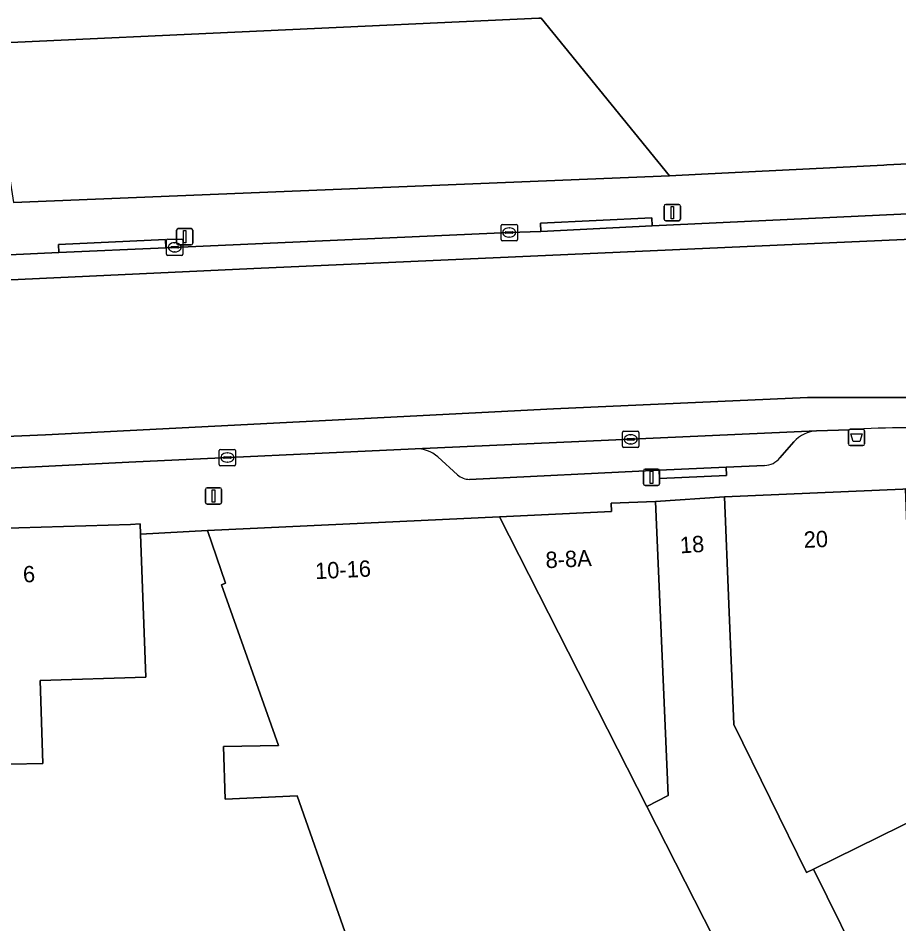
# Model space of a CAD drawing. Extents: x 161087 to 161926, y 382572 to 383873.
# Drawn here: x 161793.5 to 161847.4, y 382804.9 to 382860.4 of the extents above; entities that cross this region are included whole.
import ezdxf

# ---------------------------------------------------------------- set-up
doc = ezdxf.new("R2010")
doc.units = 0
for name, color, linetype in [('IMGEO_Afvalbak', 7, 'Continuous'), ('IMGEO_Erf', 7, 'Continuous'), ('IMGEO_Kolk', 7, 'Continuous'), ('IMGEO_Lichtmast', 7, 'Continuous'), ('IMGEO_Pand', 7, 'Continuous'), ('IMGEO_Pand_nummerreeks', 7, 'Continuous'), ('IMGEO_Parkeervlak_open', 7, 'Continuous'), ('IMGEO_Rijbaan_lokaal_gesloten', 7, 'Continuous'), ('IMGEO_Voetpad_open', 7, 'Continuous')]:
    doc.layers.add(name, color=color, linetype=linetype)

msp = doc.modelspace()

# ---------------------------------------------------------------- linework, layer by layer
at = {"layer": 'IMGEO_Afvalbak'}
for p, q in [((161844.265, 382834.304), (161844.265, 382835.104)), ((161844.265, 382835.104), (161844.265, 382834.304)), ((161844.365, 382835.204), (161845.155, 382835.204)), ((161845.155, 382835.204), (161844.365, 382835.204)), ((161845.255, 382835.104), (161845.255, 382834.304)), ((161845.255, 382834.304), (161845.255, 382835.104)), ((161845.155, 382834.204), (161844.365, 382834.204)), ((161844.365, 382834.204), (161845.155, 382834.204))]:
    msp.add_line(p, q, dxfattribs=at)
msp.add_lwpolyline([(161844.408, 382834.918), (161845.112, 382834.918), (161844.963, 382834.448), (161844.557, 382834.448), (161844.408, 382834.918)], dxfattribs=at)
for centre, start, end in [((161844.365, 382835.104), 90, 180), ((161844.365, 382835.104), 90, 180), ((161845.155, 382835.104), 0, 90), ((161845.155, 382835.104), 360, 90), ((161844.365, 382834.304), 180, 270), ((161844.365, 382834.304), 180, 270), ((161845.155, 382834.304), 270, 0), ((161845.155, 382834.304), 270, 0)]:
    msp.add_arc(centre, 0.1, start, end, dxfattribs=at)
at = {"layer": 'IMGEO_Erf'}
for points in [[(161833.32, 382850.708), (161825.459, 382860.359), (161825.324, 382860.352), (161791.643, 382858.806), (161793.173, 382849.087)], [(161852.198, 382804.529), (161855.299, 382804.359), (161860.305, 382804.076), (161860.365, 382805.353), (161855.823, 382805.577), (161852.005, 382813.152), (161851.488, 382812.897), (161842.133, 382808.291), (161845.493, 382801.467), (161846.073, 382800.288), (161849.93, 382792.454), (161851.597, 382792.363)]]:
    msp.add_lwpolyline(points, close=True, dxfattribs=at)
msp.add_lwpolyline([(161822.714, 382743.348), (161811.318, 382763.682), (161808.664, 382768.534), (161824.514, 382775.865), (161826.285, 382772.036), (161846.952, 382781.596), (161845.17, 382785.236), (161839.913, 382795.976), (161819.584, 382787.007), (161810.521, 382812.78), (161806.114, 382812.578), (161806.021, 382815.797), (161809.397, 382815.85), (161805.892, 382825.687), (161806.149, 382825.781), (161805.053, 382829.003), (161800.95, 382828.783), (161801.106, 382824.375), (161801.26, 382820.026), (161794.798, 382819.842), (161794.957, 382814.762), (161790.979, 382814.663)], dxfattribs=at)
at = {"layer": 'IMGEO_Kolk'}
for p, q in [((161823.007, 382846.814), (161823.007, 382847.666)), ((161823.082, 382847.74), (161823.934, 382847.74)), ((161823.495, 382847.52), (161823.52, 382847.52)), ((161824.008, 382847.666), (161824.008, 382846.814)), ((161823.266, 382847.234), (161823.266, 382847.246)), ((161823.704, 382847.197), (161823.306, 382847.197)), ((161823.309, 382847.283), (161823.707, 382847.283)), ((161823.518, 382846.96), (161823.493, 382846.96)), ((161823.75, 382847.246), (161823.75, 382847.234)), ((161802.539, 382845.911), (161802.539, 382846.763)), ((161802.614, 382846.837), (161803.466, 382846.837)), ((161803.027, 382846.617), (161803.052, 382846.617)), ((161803.54, 382846.763), (161803.54, 382845.911)), ((161823.934, 382846.74), (161823.082, 382846.74)), ((161803.466, 382845.837), (161802.614, 382845.837)), ((161802.798, 382846.331), (161802.798, 382846.343)), ((161803.236, 382846.294), (161802.838, 382846.294)), ((161802.841, 382846.38), (161803.239, 382846.38)), ((161803.05, 382846.057), (161803.025, 382846.057)), ((161803.282, 382846.343), (161803.282, 382846.331)), ((161830.441, 382834.163), (161830.441, 382835.015)), ((161830.516, 382835.089), (161831.368, 382835.089)), ((161830.929, 382834.869), (161830.954, 382834.869)), ((161831.442, 382835.015), (161831.442, 382834.163)), ((161830.7, 382834.583), (161830.7, 382834.595)), ((161831.138, 382834.546), (161830.74, 382834.546)), ((161830.743, 382834.632), (161831.141, 382834.632)), ((161830.952, 382834.309), (161830.927, 382834.309)), ((161831.184, 382834.595), (161831.184, 382834.583)), ((161805.757, 382833.047), (161805.757, 382833.899)), ((161805.832, 382833.973), (161806.684, 382833.973)), ((161806.245, 382833.753), (161806.27, 382833.753)), ((161806.758, 382833.899), (161806.758, 382833.047)), ((161831.368, 382834.089), (161830.516, 382834.089)), ((161806.016, 382833.467), (161806.016, 382833.479)), ((161806.454, 382833.43), (161806.056, 382833.43)), ((161806.059, 382833.516), (161806.457, 382833.516)), ((161806.268, 382833.193), (161806.243, 382833.193)), ((161806.5, 382833.479), (161806.5, 382833.467)), ((161806.684, 382832.973), (161805.832, 382832.973))]:
    msp.add_line(p, q, dxfattribs=at)
for points in [[(161823.007, 382846.814), (161823.007, 382847.666)], [(161823.082, 382847.74), (161823.934, 382847.74)], [(161824.008, 382847.666), (161824.008, 382846.814)], [(161802.539, 382845.911), (161802.539, 382846.763)], [(161802.614, 382846.837), (161803.466, 382846.837)], [(161803.54, 382846.763), (161803.54, 382845.911)], [(161823.934, 382846.74), (161823.082, 382846.74)], [(161803.466, 382845.837), (161802.614, 382845.837)], [(161830.441, 382834.163), (161830.441, 382835.015)], [(161830.516, 382835.089), (161831.368, 382835.089)], [(161831.442, 382835.015), (161831.442, 382834.163)], [(161805.757, 382833.047), (161805.757, 382833.899)], [(161805.832, 382833.973), (161806.684, 382833.973)], [(161806.758, 382833.899), (161806.758, 382833.047)], [(161831.368, 382834.089), (161830.516, 382834.089)], [(161806.684, 382832.973), (161805.832, 382832.973)]]:
    msp.add_lwpolyline(points, dxfattribs=at)
for centre, radius, start, end in [((161823.084, 382847.664), 0.0765, 91.552, 178.448), ((161823.084, 382847.664), 0.0765, 91.552, 178.448), ((161823.932, 382847.664), 0.0765, 1.552, 88.448), ((161823.932, 382847.664), 0.0765, 1.552, 88.448), ((161823.306, 382847.243), 0.0403, 85.8775, 175.7526), ((161823.303, 382847.233), 0.0366, 178.938, 274.7102), ((161823.707, 382847.24), 0.043, 264.8664, 352.4533), ((161823.711, 382847.245), 0.0386, 1.7309, 96.639), ((161802.616, 382846.761), 0.0765, 91.552, 178.448), ((161802.616, 382846.761), 0.0765, 91.552, 178.448), ((161803.464, 382846.761), 0.0765, 1.552, 88.448), ((161803.464, 382846.761), 0.0765, 1.552, 88.448), ((161823.084, 382846.816), 0.0765, 181.552, 268.448), ((161823.084, 382846.816), 0.0765, 181.552, 268.448), ((161823.932, 382846.816), 0.0765, 271.552, 358.448), ((161823.932, 382846.816), 0.0765, 271.552, 358.448), ((161802.616, 382845.913), 0.0765, 181.552, 268.448), ((161802.616, 382845.913), 0.0765, 181.552, 268.448), ((161802.838, 382846.34), 0.0403, 85.8775, 175.7526), ((161802.835, 382846.33), 0.0366, 178.938, 274.7102), ((161803.239, 382846.337), 0.043, 264.8664, 352.4533), ((161803.243, 382846.342), 0.0386, 1.7309, 96.639), ((161803.464, 382845.913), 0.0765, 271.552, 358.448), ((161803.464, 382845.913), 0.0765, 271.552, 358.448), ((161830.518, 382835.013), 0.0765, 91.552, 178.448), ((161830.518, 382835.013), 0.0765, 91.552, 178.448), ((161831.366, 382835.013), 0.0765, 1.552, 88.448), ((161831.366, 382835.013), 0.0765, 1.552, 88.448), ((161830.74, 382834.592), 0.0403, 85.8775, 175.7526), ((161830.737, 382834.582), 0.0366, 178.938, 274.7102), ((161831.141, 382834.589), 0.043, 264.8664, 352.4533), ((161831.145, 382834.594), 0.0386, 1.7309, 96.639), ((161805.834, 382833.897), 0.0765, 91.552, 178.448), ((161805.834, 382833.897), 0.0765, 91.552, 178.448), ((161806.682, 382833.897), 0.0765, 1.552, 88.448), ((161806.682, 382833.897), 0.0765, 1.552, 88.448), ((161830.518, 382834.165), 0.0765, 181.552, 268.448), ((161830.518, 382834.165), 0.0765, 181.552, 268.448), ((161831.366, 382834.165), 0.0765, 271.552, 358.448), ((161831.366, 382834.165), 0.0765, 271.552, 358.448), ((161806.056, 382833.476), 0.0403, 85.8775, 175.7526), ((161806.053, 382833.466), 0.0366, 178.938, 274.7102), ((161806.457, 382833.473), 0.043, 264.8664, 352.4533), ((161806.461, 382833.478), 0.0386, 1.7309, 96.639), ((161805.834, 382833.049), 0.0765, 181.552, 268.448), ((161805.834, 382833.049), 0.0765, 181.552, 268.448), ((161806.682, 382833.049), 0.0765, 271.552, 358.448), ((161806.682, 382833.049), 0.0765, 271.552, 358.448)]:
    msp.add_arc(centre, radius, start, end, dxfattribs=at)
for centre, major_axis, ratio, start_param, end_param in [((161823.494, 382847.24), (-0.387, 0.002), 0.722429, 4.712389, 7.853982), ((161823.519, 382847.24), (-0.39, 0.002), 0.717154, 1.570796, 4.712389), ((161803.026, 382846.337), (-0.387, 0.002), 0.722429, 4.712389, 7.853982), ((161803.051, 382846.337), (-0.39, 0.002), 0.717154, 1.570796, 4.712389), ((161830.928, 382834.589), (-0.387, 0.002), 0.722429, 4.712389, 7.853982), ((161830.953, 382834.589), (-0.39, 0.002), 0.717154, 1.570796, 4.712389), ((161806.244, 382833.473), (-0.387, 0.002), 0.722429, 4.712389, 7.853982), ((161806.269, 382833.473), (-0.39, 0.002), 0.717154, 1.570796, 4.712389)]:
    msp.add_ellipse(centre, major_axis=major_axis, ratio=ratio, start_param=start_param, end_param=end_param, dxfattribs=at)
at = {"layer": 'IMGEO_Lichtmast'}
for p, q in [((161832.991, 382848.063), (161832.991, 382848.863)), ((161832.991, 382848.863), (161832.991, 382848.063)), ((161833.091, 382848.963), (161833.881, 382848.963)), ((161833.881, 382848.963), (161833.091, 382848.963)), ((161833.981, 382848.863), (161833.981, 382848.063)), ((161833.981, 382848.063), (161833.981, 382848.863)), ((161833.881, 382847.963), (161833.091, 382847.963)), ((161833.091, 382847.963), (161833.881, 382847.963)), ((161803.152, 382846.58), (161803.152, 382847.38)), ((161803.152, 382847.38), (161803.152, 382846.58)), ((161803.252, 382847.48), (161804.042, 382847.48)), ((161804.042, 382847.48), (161803.252, 382847.48)), ((161804.142, 382847.38), (161804.142, 382846.58)), ((161804.142, 382846.58), (161804.142, 382847.38)), ((161804.042, 382846.48), (161803.252, 382846.48)), ((161803.252, 382846.48), (161804.042, 382846.48)), ((161831.721, 382831.868), (161831.721, 382832.668)), ((161831.721, 382832.668), (161831.721, 382831.868)), ((161831.821, 382832.768), (161832.611, 382832.768)), ((161832.611, 382832.768), (161831.821, 382832.768)), ((161832.711, 382832.668), (161832.711, 382831.868)), ((161832.711, 382831.868), (161832.711, 382832.668)), ((161804.914, 382830.725), (161804.914, 382831.525)), ((161804.914, 382831.525), (161804.914, 382830.725)), ((161805.014, 382831.625), (161805.804, 382831.625)), ((161805.804, 382831.625), (161805.014, 382831.625)), ((161805.904, 382831.525), (161805.904, 382830.725)), ((161805.904, 382830.725), (161805.904, 382831.525)), ((161832.611, 382831.768), (161831.821, 382831.768)), ((161831.821, 382831.768), (161832.611, 382831.768)), ((161805.804, 382830.625), (161805.014, 382830.625)), ((161805.014, 382830.625), (161805.804, 382830.625))]:
    msp.add_line(p, q, dxfattribs=at)
for points in [[(161833.411, 382848.838), (161833.561, 382848.838), (161833.561, 382848.088), (161833.411, 382848.088), (161833.411, 382848.838)], [(161803.572, 382847.355), (161803.722, 382847.355), (161803.722, 382846.605), (161803.572, 382846.605), (161803.572, 382847.355)], [(161832.141, 382832.643), (161832.291, 382832.643), (161832.291, 382831.893), (161832.141, 382831.893), (161832.141, 382832.643)], [(161805.334, 382831.5), (161805.484, 382831.5), (161805.484, 382830.75), (161805.334, 382830.75), (161805.334, 382831.5)]]:
    msp.add_lwpolyline(points, dxfattribs=at)
for centre, start, end in [((161833.091, 382848.863), 90, 180), ((161833.091, 382848.863), 90, 180), ((161833.881, 382848.863), 0, 90), ((161833.881, 382848.863), 360, 90), ((161833.091, 382848.063), 180, 270), ((161833.091, 382848.063), 180, 270), ((161833.881, 382848.063), 270, 0), ((161833.881, 382848.063), 270, 0), ((161803.252, 382847.38), 90, 180), ((161803.252, 382847.38), 90, 180), ((161804.042, 382847.38), 0, 90), ((161804.042, 382847.38), 360, 90), ((161803.252, 382846.58), 180, 270), ((161803.252, 382846.58), 180, 270), ((161804.042, 382846.58), 270, 0), ((161804.042, 382846.58), 270, 0), ((161831.821, 382832.668), 90, 180), ((161831.821, 382832.668), 90, 180), ((161832.611, 382832.668), 0, 90), ((161832.611, 382832.668), 360, 90), ((161805.014, 382831.525), 90, 180), ((161805.014, 382831.525), 90, 180), ((161805.804, 382831.525), 0, 90), ((161805.804, 382831.525), 360, 90), ((161831.821, 382831.868), 180, 270), ((161831.821, 382831.868), 180, 270), ((161832.611, 382831.868), 270, 0), ((161832.611, 382831.868), 270, 0), ((161805.014, 382830.725), 180, 270), ((161805.014, 382830.725), 180, 270), ((161805.804, 382830.725), 270, 0), ((161805.804, 382830.725), 270, 0)]:
    msp.add_arc(centre, 0.1, start, end, dxfattribs=at)
at = {"layer": 'IMGEO_Pand'}
msp.add_lwpolyline([(161791.643, 382858.806), (161825.324, 382860.352), (161825.459, 382860.359), (161833.32, 382850.708), (161835.282, 382850.802), (161846.429, 382851.37), (161846.616, 382851.379), (161861.213, 382852.08)], dxfattribs=at)
for points in [[(161848.168, 382820.764), (161847.76, 382831.552), (161847.588, 382831.545), (161836.688, 382831.067), (161836.95, 382824.507), (161837.245, 382817.14), (161841.698, 382808.077), (161842.133, 382808.291), (161851.488, 382812.897), (161852.005, 382813.152)], [(161837.245, 382817.14), (161836.95, 382824.507), (161836.688, 382831.067), (161832.463, 382830.793), (161833.228, 382812.79), (161831.931, 382812.13), (161840.106, 382796.061), (161839.913, 382795.976), (161845.17, 382785.236), (161846.47, 382785.875), (161847.085, 382785.83), (161852, 382788.25), (161849.93, 382792.454), (161846.073, 382800.288), (161845.493, 382801.467), (161842.133, 382808.291), (161841.698, 382808.077)], [(161831.931, 382812.13), (161833.228, 382812.79), (161832.463, 382830.793), (161829.74, 382830.675), (161829.775, 382830.173), (161822.916, 382829.848)], [(161839.913, 382795.976), (161840.106, 382796.061), (161831.931, 382812.13), (161822.916, 382829.848), (161805.053, 382829.003), (161806.149, 382825.781), (161805.892, 382825.687), (161809.397, 382815.85), (161806.021, 382815.797), (161806.114, 382812.578), (161810.521, 382812.78), (161819.584, 382787.007)], [(161800.95, 382828.783), (161800.928, 382829.412), (161800.329, 382829.386), (161790.746, 382829.084), (161787.585, 382828.984), (161787.977, 382818.963), (161789.696, 382819.03), (161790.979, 382814.663), (161794.957, 382814.762), (161794.798, 382819.842), (161801.26, 382820.026), (161801.106, 382824.375)]]:
    msp.add_lwpolyline(points, close=True, dxfattribs=at)
at = {"layer": 'IMGEO_Parkeervlak_open'}
for points in [[(161842.321, 382835.109), (161830.942, 382834.589), (161817.761, 382834.014)], [(161840.072, 382833.457), (161840.927, 382834.437)], [(161819.142, 382833.507), (161820.352, 382832.409)], [(161821.079, 382832.135), (161832.683, 382832.692), (161836.777, 382832.881), (161839.131, 382832.989)]]:
    msp.add_lwpolyline(points, dxfattribs=at)
for centre, radius, start, end in [((161842.459, 382833.041), 2.073, 93.8186, 137.6557), ((161817.82, 382832.039), 1.976, 47.9821, 91.699), ((161839.098, 382834.236), 1.248, 271.5352, 321.3511), ((161821.105, 382833.306), 1.171, 229.9767, 268.7213)]:
    msp.add_arc(centre, radius, start, end, dxfattribs=at)
at = {"layer": 'IMGEO_Rijbaan_lokaal_gesloten'}
for points in [[(161862.869, 382848.994), (161854.439, 382848.685), (161832.263, 382847.644), (161825.44, 382847.308), (161823.504, 382847.238), (161802.492, 382846.312), (161795.948, 382846.019), (161792.902, 382845.883), (161788.246, 382845.674), (161787.54, 382845.621), (161786.758, 382845.61), (161784.962, 382845.502), (161786.091, 382844.033), (161787.742, 382844.105), (161807.883, 382845.036), (161855.93, 382847.19)], [(161856.563, 382842.678), (161855.679, 382842.542), (161855.707, 382842.799), (161855.93, 382847.19), (161807.883, 382845.036), (161787.742, 382844.105), (161786.091, 382844.033)], [(161841.766, 382837.156), (161855.272, 382837.15), (161855.451, 382839.166), (161855.46, 382839.39), (161865.12, 382838.895), (161865.445, 382843.847), (161862.497, 382843.541)], [(161786.082, 382843.125), (161783.978, 382842.401), (161777.336, 382840.072), (161764.885, 382835.707), (161764.683, 382835.636), (161752.01, 382831.223), (161741.488, 382827.556), (161736.346, 382825.698), (161735.002, 382825.222), (161737.362, 382819.209), (161767.109, 382829.547), (161774.717, 382832.23), (161779.972, 382833.544), (161784.515, 382834.256), (161788.346, 382834.584), (161795.133, 382834.857), (161826.222, 382836.445), (161841.766, 382837.156)], [(161862.326, 382835.817), (161858.94, 382837.052), (161855.272, 382837.15), (161841.766, 382837.156), (161826.222, 382836.445), (161795.133, 382834.857), (161788.346, 382834.584), (161784.515, 382834.256), (161779.972, 382833.544), (161774.717, 382832.23), (161767.109, 382829.547), (161737.362, 382819.209), (161737.856, 382817.95), (161766.768, 382827.835), (161768.826, 382828.505), (161772.113, 382829.631)], [(161787.956, 382832.571), (161800.222, 382833.189), (161817.761, 382834.014), (161830.942, 382834.589), (161842.321, 382835.109), (161844.339, 382835.171)]]:
    msp.add_lwpolyline(points, dxfattribs=at)
msp.add_arc((161848.201, 382777.912), 57.389, 86.84331, 93.8584, dxfattribs=at)
at = {"layer": 'IMGEO_Voetpad_open'}
for points in [[(161792.902, 382845.883), (161795.948, 382846.019), (161795.926, 382846.518), (161802.47, 382846.811), (161802.492, 382846.312), (161823.504, 382847.238), (161825.44, 382847.308), (161825.416, 382847.807), (161832.239, 382848.143), (161832.263, 382847.644), (161854.439, 382848.685), (161862.869, 382848.994), (161861.574, 382851.99), (161861.448, 382851.971), (161861.326, 382851.991), (161861.213, 382852.08), (161846.616, 382851.379), (161846.429, 382851.37), (161835.282, 382850.802), (161833.32, 382850.708), (161793.173, 382849.087)], [(161844.339, 382835.171), (161842.321, 382835.109)], [(161840.927, 382834.437), (161840.072, 382833.457)], [(161817.761, 382834.014), (161800.222, 382833.189), (161787.956, 382832.571)], [(161790.746, 382829.084), (161800.329, 382829.386), (161800.928, 382829.412), (161800.95, 382828.783), (161805.053, 382829.003), (161822.916, 382829.848), (161829.775, 382830.173), (161829.74, 382830.675), (161832.463, 382830.793), (161836.688, 382831.067), (161847.588, 382831.545), (161847.76, 382831.552), (161859.687, 382832.064), (161861.808, 382830.019), (161862.575, 382833.596)], [(161820.352, 382832.409), (161819.142, 382833.507)], [(161839.131, 382832.989), (161836.777, 382832.881), (161836.8, 382832.382), (161832.706, 382832.193), (161832.683, 382832.692), (161821.079, 382832.135)]]:
    msp.add_lwpolyline(points, dxfattribs=at)
for points in [[(161825.44, 382847.308), (161832.263, 382847.644), (161832.239, 382848.143), (161825.416, 382847.807)], [(161802.492, 382846.312), (161802.47, 382846.811), (161795.926, 382846.518), (161795.948, 382846.019)], [(161836.777, 382832.881), (161832.683, 382832.692), (161832.706, 382832.193), (161836.8, 382832.382)]]:
    msp.add_lwpolyline(points, close=True, dxfattribs=at)
for centre, radius, start, end in [((161842.459, 382833.041), 2.073, 93.8186, 137.6557), ((161848.201, 382777.912), 57.389, 86.84331, 93.8584), ((161817.82, 382832.039), 1.976, 47.9821, 91.699), ((161839.098, 382834.236), 1.248, 271.5352, 321.3511), ((161821.105, 382833.306), 1.171, 229.9767, 268.7213)]:
    msp.add_arc(centre, radius, start, end, dxfattribs=at)

# ---------------------------------------------------------------- texts
at = {"layer": 'IMGEO_Pand_nummerreeks'}
for s, rotation, p in [('18', 3.7185, (161833.987, 382827.607)), ('20', 2.3205, (161841.552, 382827.945)), ('8-8A', 2.7096, (161825.754, 382826.699)), ('10-16', 2.7096, (161811.65, 382826.031)), ('6', 2.4412, (161793.768, 382825.824))]:
    msp.add_text(s, height=1, rotation=rotation, dxfattribs=at).set_placement(p)

doc.saveas('drawing.dxf')
